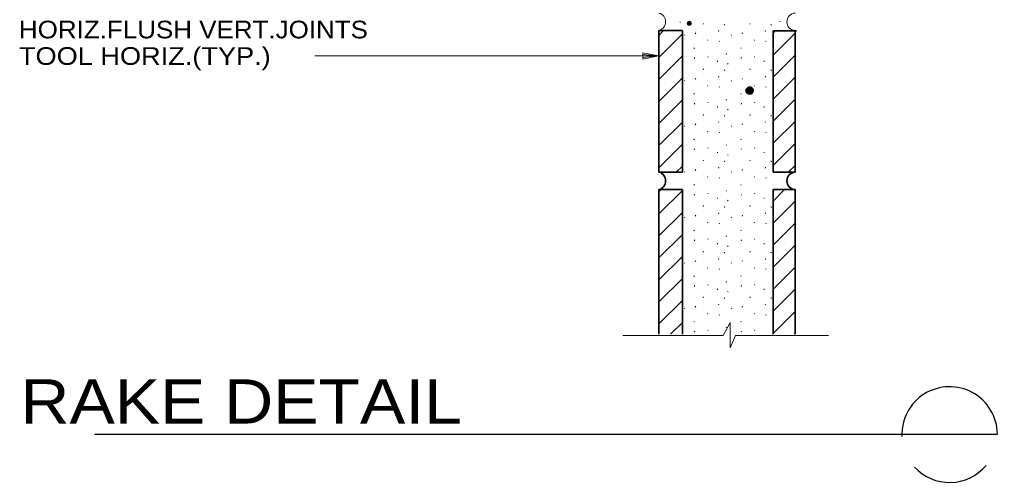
# Model space of a CAD drawing. Extents: x 11001.56 to 11007.08, y 10014.75 to 10021.39.
# Drawn here: x 11001.56 to 11006.8, y 10014.75 to 10017.22 of the extents above; entities that cross this region are included whole.
import ezdxf

# ---------------------------------------------------------------- set-up
doc = ezdxf.new("R2010")
doc.units = 0
doc.header["$LTSCALE"] = 0.038
doc.header["$PDMODE"] = 32
doc.header["$PDSIZE"] = 0.019
for name, color, linetype, lineweight in [('1', 7, 'Continuous', 13), ('46', 7, 'Continuous', 35), ('47', 7, 'Continuous', 25), ('54', 7, 'Continuous', 35)]:
    doc.layers.add(name, color=color, linetype=linetype, lineweight=lineweight)

msp = doc.modelspace()

# ---------------------------------------------------------------- linework, layer by layer
at = {"layer": '1'}
for p, q in [((11005.22056, 10017.19649), (11005.22266, 10017.20119)), ((11005.33278, 10017.19648), (11005.33486, 10017.19335)), ((11005.33486, 10017.19529), (11005.33695, 10017.19216)), ((11005.47056, 10017.19649), (11005.47266, 10017.20119)), ((11005.58278, 10017.19648), (11005.58486, 10017.19335)), ((11005.58486, 10017.19529), (11005.58695, 10017.19216)), ((11004.9845, 10017.13807), (11005.00701, 10017.16058)), ((11004.9845, 10017.02022), (11005.1091, 10017.14482)), ((11005.17829, 10017.14579), (11005.18037, 10017.15049)), ((11005.30198, 10017.15779), (11005.30407, 10017.16249)), ((11005.42829, 10017.14579), (11005.43037, 10017.15049)), ((11005.55198, 10017.15779), (11005.55407, 10017.16249)), ((11005.59473, 10017.14872), (11005.6066, 10017.16058)), ((11005.59473, 10017.03086), (11005.71231, 10017.14845)), ((11005.11987, 10017.1397), (11005.12196, 10017.13656)), ((11005.24353, 10017.1124), (11005.24561, 10017.10926)), ((11005.30521, 10017.10675), (11005.30729, 10017.10361)), ((11005.36987, 10017.1397), (11005.37196, 10017.13656)), ((11005.49353, 10017.1124), (11005.49561, 10017.10926)), ((11005.55521, 10017.10675), (11005.55729, 10017.10361)), ((11005.17135, 10017.06968), (11005.17345, 10017.06654)), ((11005.34374, 10017.03462), (11005.34583, 10017.03932)), ((11005.42135, 10017.06968), (11005.42345, 10017.06654)), ((11005.59374, 10017.03462), (11005.59472, 10017.03685)), ((11004.9845, 10016.90236), (11005.1091, 10017.02697)), ((11005.17307, 10017.01323), (11005.17516, 10017.01793)), ((11005.24549, 10017.02334), (11005.24757, 10017.02021)), ((11005.29716, 10017.00012), (11005.29768, 10016.99543)), ((11005.35134, 10016.98628), (11005.35343, 10016.98315)), ((11005.42307, 10017.01323), (11005.42516, 10017.01793)), ((11005.49549, 10017.02334), (11005.49757, 10017.02021)), ((11005.54716, 10017.00012), (11005.54768, 10016.99543)), ((11005.59473, 10016.91301), (11005.71231, 10017.03059)), ((11005.22056, 10016.95269), (11005.22266, 10016.95739)), ((11005.33278, 10016.95268), (11005.33486, 10016.94955)), ((11005.33486, 10016.95149), (11005.33695, 10016.94835)), ((11005.47056, 10016.95269), (11005.47266, 10016.95739)), ((11005.58278, 10016.95268), (11005.58486, 10016.94955)), ((11005.58486, 10016.95149), (11005.58695, 10016.94835)), ((11004.9845, 10016.78452), (11005.1091, 10016.90912)), ((11005.11987, 10016.8959), (11005.12196, 10016.89276)), ((11005.17829, 10016.90199), (11005.18037, 10016.90669)), ((11005.30198, 10016.91399), (11005.30407, 10016.91869)), ((11005.36987, 10016.8959), (11005.37196, 10016.89276)), ((11005.42829, 10016.90199), (11005.43037, 10016.90669)), ((11005.55198, 10016.91399), (11005.55407, 10016.91869)), ((11005.59473, 10016.79516), (11005.71231, 10016.91275)), ((11005.24353, 10016.86859), (11005.24561, 10016.86546)), ((11005.30521, 10016.86295), (11005.30729, 10016.85981)), ((11005.49353, 10016.86859), (11005.49561, 10016.86546)), ((11005.55521, 10016.86295), (11005.55729, 10016.85981)), ((11004.9845, 10016.66668), (11005.1091, 10016.79127)), ((11005.17135, 10016.82587), (11005.17345, 10016.82274)), ((11005.24549, 10016.77954), (11005.24757, 10016.77641)), ((11005.34374, 10016.79082), (11005.34583, 10016.79552)), ((11005.42135, 10016.82587), (11005.42345, 10016.82274)), ((11005.49549, 10016.77954), (11005.49757, 10016.77641)), ((11005.59374, 10016.79082), (11005.59473, 10016.79305)), ((11005.59473, 10016.67731), (11005.71231, 10016.7949)), ((11005.17307, 10016.76943), (11005.17516, 10016.77412)), ((11005.29716, 10016.75632), (11005.29768, 10016.75162)), ((11005.35134, 10016.74248), (11005.35343, 10016.73934)), ((11005.42307, 10016.76943), (11005.42516, 10016.77412)), ((11005.54716, 10016.75632), (11005.54768, 10016.75162)), ((11004.9845, 10016.54882), (11005.1091, 10016.67342)), ((11005.22056, 10016.70889), (11005.22266, 10016.71358)), ((11005.30198, 10016.67019), (11005.30407, 10016.67489)), ((11005.33278, 10016.70887), (11005.33486, 10016.70575)), ((11005.33486, 10016.70769), (11005.33695, 10016.70455)), ((11005.47056, 10016.70889), (11005.47266, 10016.71358)), ((11005.55198, 10016.67019), (11005.55407, 10016.67489)), ((11005.58278, 10016.70887), (11005.58486, 10016.70575)), ((11005.58486, 10016.70769), (11005.58695, 10016.70455)), ((11005.59473, 10016.55946), (11005.71231, 10016.67704)), ((11005.11987, 10016.65209), (11005.12196, 10016.64896)), ((11005.17829, 10016.65819), (11005.18037, 10016.66289)), ((11005.24353, 10016.62479), (11005.24561, 10016.62166)), ((11005.30521, 10016.61915), (11005.30729, 10016.61601)), ((11005.36987, 10016.65209), (11005.37196, 10016.64896)), ((11005.42829, 10016.65819), (11005.43037, 10016.66289)), ((11005.49353, 10016.62479), (11005.49561, 10016.62166)), ((11005.55521, 10016.61915), (11005.55729, 10016.61601)), ((11005.17135, 10016.58207), (11005.17345, 10016.57894)), ((11005.42135, 10016.58207), (11005.42345, 10016.57894)), ((11004.9845, 10016.43097), (11005.1091, 10016.55557)), ((11005.17307, 10016.52562), (11005.17516, 10016.53032)), ((11005.24549, 10016.53574), (11005.24757, 10016.5326)), ((11005.34374, 10016.54702), (11005.34583, 10016.55172)), ((11005.42307, 10016.52562), (11005.42516, 10016.53032)), ((11005.49549, 10016.53574), (11005.49757, 10016.5326)), ((11005.59374, 10016.54702), (11005.59473, 10016.54925)), ((11005.59473, 10016.4416), (11005.71231, 10016.5592)), ((11005.22056, 10016.46508), (11005.22266, 10016.46978)), ((11005.29716, 10016.51252), (11005.29768, 10016.50782)), ((11005.33278, 10016.46507), (11005.33486, 10016.46195)), ((11005.33486, 10016.46389), (11005.33695, 10016.46075)), ((11005.35134, 10016.49868), (11005.35343, 10016.49554)), ((11005.47056, 10016.46508), (11005.47266, 10016.46978)), ((11005.54716, 10016.51252), (11005.54768, 10016.50782)), ((11005.58278, 10016.46507), (11005.58486, 10016.46195)), ((11005.58486, 10016.46389), (11005.58695, 10016.46075)), ((11005.07669, 10016.40531), (11005.1091, 10016.43772)), ((11005.11987, 10016.40829), (11005.12196, 10016.40516)), ((11005.17829, 10016.41439), (11005.18037, 10016.41908)), ((11005.30198, 10016.42639), (11005.30407, 10016.43108)), ((11005.36987, 10016.40829), (11005.37196, 10016.40516)), ((11005.42829, 10016.41439), (11005.43037, 10016.41908)), ((11005.55198, 10016.42639), (11005.55407, 10016.43108)), ((11005.67628, 10016.40531), (11005.71231, 10016.44134)), ((11005.24353, 10016.38099), (11005.24561, 10016.37785)), ((11005.30521, 10016.37534), (11005.30729, 10016.37221)), ((11005.49353, 10016.38099), (11005.49561, 10016.37785)), ((11005.55521, 10016.37534), (11005.55729, 10016.37221)), ((11004.9839, 10016.30045), (11004.99502, 10016.31156)), ((11004.9839, 10016.18259), (11005.1091, 10016.30779)), ((11005.17135, 10016.33827), (11005.17345, 10016.33514)), ((11005.34374, 10016.30322), (11005.34583, 10016.30792)), ((11005.42135, 10016.33827), (11005.42345, 10016.33514)), ((11005.59374, 10016.30322), (11005.59473, 10016.30545)), ((11005.59473, 10016.25008), (11005.6562, 10016.31156)), ((11005.17307, 10016.28182), (11005.17516, 10016.28652)), ((11005.24549, 10016.29194), (11005.24757, 10016.2888)), ((11005.29716, 10016.26872), (11005.29768, 10016.26402)), ((11005.35134, 10016.25487), (11005.35343, 10016.25174)), ((11005.42307, 10016.28182), (11005.42516, 10016.28652)), ((11005.49549, 10016.29194), (11005.49757, 10016.2888)), ((11005.54716, 10016.26872), (11005.54768, 10016.26402)), ((11005.22056, 10016.22128), (11005.22266, 10016.22598)), ((11005.33278, 10016.22127), (11005.33486, 10016.21815)), ((11005.33486, 10016.22008), (11005.33695, 10016.21695)), ((11005.47056, 10016.22128), (11005.47266, 10016.22598)), ((11005.58278, 10016.22127), (11005.58486, 10016.21815)), ((11005.58486, 10016.22008), (11005.58695, 10016.21695)), ((11005.59473, 10016.13223), (11005.71231, 10016.24982)), ((11004.9839, 10016.06474), (11005.10909, 10016.18994)), ((11005.11987, 10016.16449), (11005.12196, 10016.16135)), ((11005.17829, 10016.17058), (11005.18037, 10016.17528)), ((11005.30198, 10016.18258), (11005.30407, 10016.18728)), ((11005.36987, 10016.16449), (11005.37196, 10016.16135)), ((11005.42829, 10016.17058), (11005.43037, 10016.17528)), ((11005.55198, 10016.18258), (11005.55407, 10016.18728)), ((11005.17135, 10016.09447), (11005.17345, 10016.09133)), ((11005.24353, 10016.13719), (11005.24561, 10016.13405)), ((11005.30521, 10016.13154), (11005.30729, 10016.12841)), ((11005.42135, 10016.09447), (11005.42345, 10016.09133)), ((11005.49353, 10016.13719), (11005.49561, 10016.13405)), ((11005.55521, 10016.13154), (11005.55729, 10016.12841)), ((11005.59472, 10016.01437), (11005.71231, 10016.13197)), ((11004.9839, 10015.94689), (11005.10909, 10016.07208)), ((11005.17307, 10016.03802), (11005.17516, 10016.04272)), ((11005.24549, 10016.04814), (11005.24757, 10016.045)), ((11005.34374, 10016.05942), (11005.34583, 10016.06411)), ((11005.42307, 10016.03802), (11005.42516, 10016.04272)), ((11005.49549, 10016.04814), (11005.49757, 10016.045)), ((11005.59374, 10016.05942), (11005.59473, 10016.06165)), ((11005.29716, 10016.02492), (11005.29768, 10016.02022)), ((11005.35134, 10016.01107), (11005.35343, 10016.00794)), ((11005.54716, 10016.02492), (11005.54768, 10016.02022)), ((11005.59473, 10015.89653), (11005.71231, 10016.01411)), ((11004.9839, 10015.82904), (11005.10909, 10015.95423)), ((11005.22056, 10015.97748), (11005.22266, 10015.98218)), ((11005.30198, 10015.93878), (11005.30407, 10015.94348)), ((11005.33278, 10015.97747), (11005.33486, 10015.97434)), ((11005.33486, 10015.97628), (11005.33695, 10015.97315)), ((11005.47056, 10015.97748), (11005.47266, 10015.98218)), ((11005.55198, 10015.93878), (11005.55407, 10015.94348)), ((11005.58278, 10015.97747), (11005.58486, 10015.97434)), ((11005.58486, 10015.97628), (11005.58695, 10015.97315)), ((11005.11987, 10015.92069), (11005.12196, 10015.91755)), ((11005.17829, 10015.92678), (11005.18037, 10015.93148)), ((11005.24353, 10015.89339), (11005.24561, 10015.89025)), ((11005.30521, 10015.88774), (11005.30729, 10015.8846)), ((11005.36987, 10015.92069), (11005.37196, 10015.91755)), ((11005.42829, 10015.92678), (11005.43037, 10015.93148)), ((11005.49353, 10015.89339), (11005.49561, 10015.89025)), ((11005.55521, 10015.88774), (11005.55729, 10015.8846)), ((11005.59474, 10015.77869), (11005.71231, 10015.89626)), ((11004.9839, 10015.71119), (11005.1091, 10015.83639)), ((11005.17135, 10015.85067), (11005.17345, 10015.84753)), ((11005.42135, 10015.85067), (11005.42345, 10015.84753)), ((11005.17307, 10015.79422), (11005.17516, 10015.79892)), ((11005.24549, 10015.80433), (11005.24757, 10015.8012)), ((11005.29716, 10015.78111), (11005.29768, 10015.77642)), ((11005.34374, 10015.81561), (11005.34583, 10015.82031)), ((11005.42307, 10015.79422), (11005.42516, 10015.79892)), ((11005.49549, 10015.80433), (11005.49757, 10015.8012)), ((11005.54716, 10015.78111), (11005.54768, 10015.77642)), ((11005.59374, 10015.81561), (11005.59472, 10015.81784)), ((11005.22056, 10015.73368), (11005.22266, 10015.73837)), ((11005.33278, 10015.73367), (11005.33486, 10015.73054)), ((11005.33486, 10015.73248), (11005.33695, 10015.72934)), ((11005.35134, 10015.76727), (11005.35343, 10015.76414)), ((11005.47056, 10015.73368), (11005.47266, 10015.73837)), ((11005.58278, 10015.73367), (11005.58486, 10015.73054)), ((11005.58486, 10015.73248), (11005.58695, 10015.72934)), ((11005.59473, 10015.66083), (11005.71231, 10015.77842)), ((11004.9839, 10015.59333), (11005.1091, 10015.71854)), ((11005.11987, 10015.67689), (11005.12196, 10015.67375)), ((11005.17829, 10015.68298), (11005.18037, 10015.68768)), ((11005.30198, 10015.69498), (11005.30407, 10015.69968)), ((11005.36987, 10015.67689), (11005.37196, 10015.67375)), ((11005.42829, 10015.68298), (11005.43037, 10015.68768)), ((11005.55198, 10015.69498), (11005.55407, 10015.69968)), ((11005.24353, 10015.64958), (11005.24561, 10015.64645)), ((11005.30521, 10015.64394), (11005.30729, 10015.6408)), ((11005.49353, 10015.64958), (11005.49561, 10015.64645)), ((11005.55521, 10015.64394), (11005.55729, 10015.6408)), ((11005.59473, 10015.54298), (11005.71231, 10015.66056)), ((11005.04639, 10015.53798), (11005.1091, 10015.60069)), ((11005.17135, 10015.60686), (11005.17345, 10015.60373)), ((11005.32704, 10015.53094), (11005.36504, 10015.6016)), ((11005.34374, 10015.57181), (11005.34583, 10015.57651)), ((11005.36504, 10015.46618), (11005.36504, 10015.6016)), ((11005.42135, 10015.60686), (11005.42345, 10015.60373)), ((11005.59374, 10015.57181), (11005.59473, 10015.57404)), ((11004.79023, 10015.53094), (11005.32704, 10015.53094)), ((11005.17307, 10015.55042), (11005.17516, 10015.55511)), ((11005.24549, 10015.56053), (11005.24757, 10015.5574)), ((11005.36504, 10015.46618), (11005.39353, 10015.53094)), ((11005.39353, 10015.53094), (11005.89156, 10015.53094)), ((11005.42307, 10015.55042), (11005.42516, 10015.55511)), ((11005.49549, 10015.56053), (11005.49757, 10015.5574)), ((11005.70758, 10015.53798), (11005.71231, 10015.54271))]:
    msp.add_line(p, q, dxfattribs=at)
at = {"layer": '1', "lineweight": 35}
for p, q in [((11004.9839, 10016.40531), (11004.9839, 10017.16278)), ((11004.9839, 10017.16278), (11005.1091, 10017.16278)), ((11005.1091, 10016.40531), (11005.1091, 10017.16058)), ((11005.59473, 10016.40531), (11005.59473, 10017.16058)), ((11005.59473, 10017.16058), (11005.71994, 10017.16058)), ((11005.71231, 10016.40531), (11005.71231, 10017.16058)), ((11004.9839, 10016.40531), (11005.1091, 10016.40531)), ((11005.59473, 10016.40531), (11005.71231, 10016.40531)), ((11004.9839, 10015.53798), (11004.9839, 10016.31156)), ((11004.9839, 10016.31156), (11005.1091, 10016.31156)), ((11005.1091, 10015.53798), (11005.1091, 10016.31156)), ((11005.59473, 10015.53798), (11005.59473, 10016.31156)), ((11005.59473, 10016.31156), (11005.71231, 10016.31156)), ((11005.71231, 10015.53798), (11005.71231, 10016.31156))]:
    msp.add_line(p, q, dxfattribs=at)
at = {"layer": '1'}
for centre, radius, start, end in [((11004.97033, 10017.20948), 0.0488, 286.1421, 73.85791), ((11005.71595, 10017.20948), 0.04702, 94.43812, 265.56187)]:
    msp.add_arc(centre, radius, start, end, dxfattribs=at)
at = {"layer": '1', "lineweight": 35}
for centre, radius, start, end in [((11004.97033, 10016.35844), 0.0488, 286.1421, 73.85791), ((11005.71595, 10016.35844), 0.04702, 94.43812, 265.56187)]:
    msp.add_arc(centre, radius, start, end, dxfattribs=at)
at = {"layer": '46', "lineweight": 13}
for p, q in [((11005.0956, 10017.20727), (11005.09876, 10017.20727)), ((11005.62868, 10017.21043), (11005.63182, 10017.21043)), ((11003.14211, 10017.0271), (11004.9807, 10017.0271)), ((11004.89736, 10017.0271), (11004.9807, 10017.0271)), ((11004.9807, 10017.0271), (11004.89736, 10017.01935))]:
    msp.add_line(p, q, dxfattribs=at)
for points in [[(11004.89736, 10017.01044), (11004.89736, 10017.04377), (11004.9807, 10017.0271)], [(11004.89736, 10017.01044), (11004.9807, 10017.0271), (11004.89736, 10017.03526)]]:
    msp.add_lwpolyline(points, dxfattribs=at)
at = {"layer": '46'}
msp.add_point((11005.14607, 10017.20096), dxfattribs=at)
at = {"layer": '47'}
msp.add_line((11006.79556, 10015.00137), (11001.96189, 10015.00137), dxfattribs=at)
for start, end in [(0.66494, 182.18413), (222.82849, 319.53834)]:
    msp.add_arc((11006.53962, 10015.00137), 0.25594, start, end, dxfattribs=at)
at = {"layer": '54'}
for centre, radius in [((11005.46875, 10016.84152), 0.01891), ((11005.46875, 10016.84138), 0.01678), ((11005.46875, 10016.84138), 0.01481), ((11005.46882, 10016.84139), 0.01282), ((11005.46875, 10016.84139), 0.01062), ((11005.46875, 10016.84139), 0.00864), ((11005.46875, 10016.84139), 0.00638), ((11005.46875, 10016.84138), 0.00425), ((11005.46875, 10016.84138), 0.00226), ((11005.46882, 10016.84139), 0.00106)]:
    msp.add_circle(centre, radius, dxfattribs=at)

# ---------------------------------------------------------------- texts
at = {"layer": '46'}
for s, width, p in [('HORIZ.FLUSH VERT.JOINTS', 1.1, (11001.55808, 10017.12082)), ('TOOL HORIZ.(TYP.)', 1.15, (11001.55808, 10016.97916))]:
    msp.add_text(s, height=0.09445, dxfattribs=dict(at, width=width)).set_placement(p)
at = {"layer": '47', "width": 1.15}
msp.add_text('   RAKE DETAIL    ', height=0.2363, dxfattribs=at).set_placement((11001.26336, 10015.06044))

doc.saveas('drawing.dxf')
